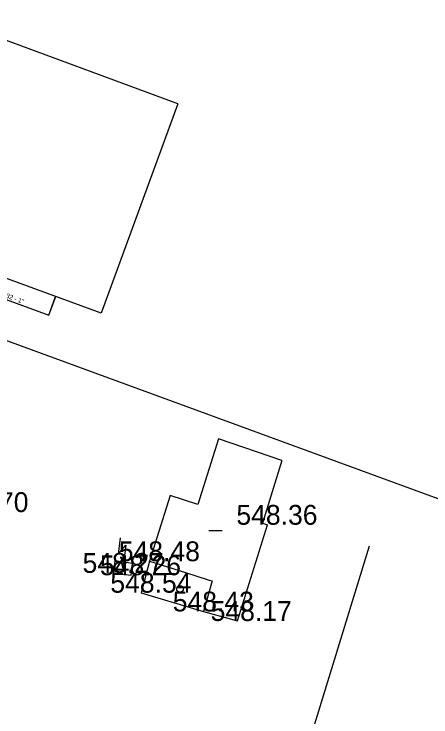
# Model space of a CAD drawing. Extents: x -669995 to -669686, y -1125551 to -1125263.
# Drawn here: x -669786.01 to -669770.25, y -1125325.67 to -1125299.08 of the extents above; entities that cross this region are included whole.
import ezdxf

# ---------------------------------------------------------------- set-up
doc = ezdxf.new("R2010")
doc.units = 0
for name, color, linetype in [('G_Bod_tecka', 7, 'Continuous'), ('G_Bod_vyska', 7, 'Continuous'), ('G_Budovy-znacky', 7, 'Continuous'), ('G_Budovy_Objekty', 7, 'Continuous'), ('G_Budovy_vstupy', 7, 'Continuous'), ('G_Ploty', 7, 'Continuous'), ('G_Site-Rozvadece', 7, 'Continuous'), ('G_Z_VODA_podz_kotovane', 7, 'Continuous'), ('Vrstva 25', 7, 'Continuous'), ('Vrstva 4', 7, 'Continuous')]:
    doc.layers.add(name, color=color, linetype=linetype)

msp = doc.modelspace()

# ---------------------------------------------------------------- linework, layer by layer
at = {"layer": 'G_Bod_tecka'}
for p, q in [((-669776.43, -1125318.4), (-669776.43, -1125318.4)), ((-669780.89, -1125319.78), (-669780.89, -1125319.78)), ((-669782.26, -1125320.22), (-669782.26, -1125320.22)), ((-669781.59, -1125320.31), (-669781.59, -1125320.31)), ((-669781.21, -1125320.97), (-669781.21, -1125320.97)), ((-669778.85, -1125321.68), (-669778.85, -1125321.68)), ((-669777.56, -1125322.04), (-669777.56, -1125322.04))]:
    msp.add_line(p, q, dxfattribs=at)
at = {"layer": 'G_Budovy-znacky'}
msp.add_line((-669778.65, -1125318.62), (-669778.15, -1125318.62), dxfattribs=at)
msp.add_circle((-669779.74, -1125320.83), 0.125, dxfattribs=at)
at = {"layer": 'G_Budovy_Objekty'}
for p, q in [((-669779.82, -1125302.48), (-669794.17, -1125297.19)), ((-669779.82, -1125302.48), (-669782.72, -1125310.4)), ((-669782.72, -1125310.4), (-669797.09, -1125305.13)), ((-669778.28, -1125315.15), (-669779.06, -1125317.63)), ((-669775.89, -1125315.97), (-669778.28, -1125315.15)), ((-669775.89, -1125315.97), (-669776.62, -1125318.34)), ((-669780.11, -1125317.3), (-669780.89, -1125319.78)), ((-669779.06, -1125317.63), (-669780.11, -1125317.3)), ((-669777.56, -1125322.04), (-669776.43, -1125318.4)), ((-669776.62, -1125318.34), (-669776.43, -1125318.4)), ((-669780.89, -1125319.78), (-669781.21, -1125320.97)), ((-669780.89, -1125319.78), (-669779.53, -1125320.21)), ((-669778.53, -1125320.52), (-669778.85, -1125321.68)), ((-669778.67, -1125320.48), (-669778.53, -1125320.52)), ((-669781.21, -1125320.97), (-669778.85, -1125321.68)), ((-669778.85, -1125321.68), (-669777.56, -1125322.04))]:
    msp.add_line(p, q, dxfattribs=at)
at = {"layer": 'G_Budovy_vstupy'}
msp.add_line((-669779.53, -1125320.21), (-669778.67, -1125320.48), dxfattribs=at)
at = {"layer": 'G_Ploty'}
msp.add_line((-669788.56, -1125310.6), (-669766.98, -1125318.52), dxfattribs=at)
msp.add_lwpolyline([(-669779.49, -1125341.71), (-669779.16, -1125340.63), (-669779.07, -1125340.34), (-669772.57, -1125319.2)], dxfattribs=at)
at = {"layer": 'G_Site-Rozvadece'}
for p, q in [((-669781.998, -1125318.891), (-669782.081, -1125319.511)), ((-669782.081, -1125319.511), (-669781.784, -1125319.173)), ((-669781.784, -1125319.173), (-669781.9, -1125320.04)), ((-669781.977, -1125319.783), (-669781.9, -1125320.04)), ((-669781.9, -1125320.04), (-669781.759, -1125319.812))]:
    msp.add_line(p, q, dxfattribs=at)
msp.add_lwpolyline([(-669782.2, -1125319.77), (-669782.26, -1125320.22), (-669781.59, -1125320.31), (-669781.53, -1125319.86)], close=True, dxfattribs=at)
at = {"layer": 'G_Z_VODA_podz_kotovane'}
msp.add_lwpolyline([(-669804.76, -1125303.6), (-669797.34, -1125305.83), (-669784.7, -1125310.47), (-669784.44, -1125309.77)], dxfattribs=at)
at = {"layer": 'Vrstva 25'}
msp.add_lwpolyline([(-669804.757, -1125303.601), (-669797.345, -1125305.832), (-669784.7, -1125310.475), (-669784.441, -1125309.771)], dxfattribs=at)

# ---------------------------------------------------------------- texts
at = {"layer": 'G_Bod_vyska'}
for s, p in [('548.70', (-669788.536, -1125317.92)), ('548.36', (-669777.608, -1125318.4)), ('548.48', (-669782.054, -1125319.78)), ('548.27', (-669783.424, -1125320.22)), ('548.26', (-669782.768, -1125320.31)), ('548.54', (-669782.374, -1125320.97)), ('548.43', (-669780.014, -1125321.68)), ('548.17', (-669778.582, -1125322.04))]:
    msp.add_text(s, height=0.75, dxfattribs=at).set_placement(p)
at = {"layer": 'Vrstva 4'}
msp.add_text('lPE 32 - 1"', height=0.17551, rotation=339.8906, dxfattribs=at).set_placement((-669786.757, -1125309.652))

doc.saveas('drawing.dxf')
